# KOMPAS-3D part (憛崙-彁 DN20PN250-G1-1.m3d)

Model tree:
1. Объединить компоненты:1  (labels: СЕНС-ПР DN20PN250-G1-1)

Referenced files in D:\Савин\!СЕНСОР\3D для заказчика\!Новый перечень\СЕНС-ПР\4. СЕНС-ПР-PN250\DN20\: СЕНС-ПР DN20PN250-G1-1.a3d
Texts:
  СЕНС-ПР DN20PN250-G1-1
  ООО НПП Сенсор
